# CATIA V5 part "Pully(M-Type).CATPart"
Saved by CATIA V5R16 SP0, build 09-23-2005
Part number: Pully
Bounding box of the stored display mesh (mm): x 0 to 54, y -42.194 to 42.194, z -42.194 to 42.194
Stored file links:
  C:\V5_education\CATIA Data\ASD\Power Transmission Gear Assembly\Assembly Data\Pully(M-Type).CATPart
  C:\V5_education\CATIA Data\ASD\Power Transmission Gear Assembly\Assembly Data\Power Transmission Gear Assembly.CATProduct
  C:\V5_education\CATIA Data\ASD\Power Transmission Gear Assembly\Assembly Data\Power Transmission Gear.CATPart
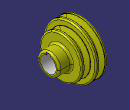
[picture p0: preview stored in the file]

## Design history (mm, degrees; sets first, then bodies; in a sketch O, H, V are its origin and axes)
Set1
  DatumSurface1: linked copy from another document
Set2 "Reference Data"
  Point1 "Center Point": (0, 0, 0)
Body1 (main body)
  Body2
    Sketch1 on zx-plane, origin (0, 0, 0), H (-1, 0, 0), V (0, 0, 1)
      axis line L1 (0, 0) -> (-72.0161, 0)
      line L2 (0, 0) -> (0, 42.2)
      line L3 (0, 42.2) -> (-4.6227, 42.2)
      line L4 (-4.6227, 42.2) -> (-7.547, 33.2)
      line L5 (-7.547, 33.2) -> (-11.453, 33.2)
      line L6 (-11.453, 33.2) -> (-14.3773, 42.2)
      point P6 (-14.3773, 42.2)
      line L7 (-14.3773, 42.2) -> (-19, 42.2)
      line L8 (-19, 42.2) -> (-19, 0)
      point P8 (-19, 0)
      construction line L9 (-19, 39.5) -> (0, 39.5)
      point P9 (-19, 39.5)
      point P10 (0, 39.5)
      construction line L10 (-9.5, 33.2) -> (-9.5, 39.5)
      point P11 (-9.5, 33.2)
      point P12 (-9.5, 39.5)
      point P13 (-13.5, 39.5)
      point P14 (-5.5, 39.5)
      distance L9 H = 39.5
      distance L3 H = 42.2
      distance L10 L2 = 9.5
      distance P13 P14 = 8
      angle L6 L4 = 36
      distance L5 L9 = 6.3
      horizontal: L1 H, L3 H, L5 H, L7 H, L9 H
      vertical: L2 V, L8 V, L10 V
      coincidence: P6 L3, P8 L1, P9 L8, P10 L2, P12 L9, L6 P13, L9 P13, L4 P14, L9 P14
      midpoint: P11 L5
      symmetry: L8 L2 L10, L6 L4 L10
    Shaft1: profile Sketch1, axis Sketch1.L1, angle 360
    Fillet1: radius 2, on edge [face of Shaft1 from Sketch1.L7 | face of Shaft1 from Sketch1.L8]; edge [face of Shaft1 from Sketch1.L2 | face of Shaft1 from Sketch1.L3]
    Fillet2: radius 1, on face of Shaft1 from Sketch1.L5
    Fillet3: radius 0.5, on edge [face of Shaft1 from Sketch1.L6 | face of Shaft1 from Sketch1.L7]; edge [face of Shaft1 from Sketch1.L3 | face of Shaft1 from Sketch1.L4]
  Assemble1: tool Body2
  Body3
    Sketch2 on zx-plane, origin (0, 0, 0), H (-1, 0, 0), V (0, 0, 1)
      axis line L1 (0, 0) -> (-72.0161, 0)
      point P2 (-15, 33.7)
      line L2 (-15, 33.7) -> (-19.6745, 33.7)
      line L3 (-19.6745, 33.7) -> (-22.4261, 24.7)
      line L4 (-22.4261, 24.7) -> (-26.5739, 24.7)
      line L5 (-26.5739, 24.7) -> (-29.3255, 33.7)
      point P6 (-29.3255, 33.7)
      line L6 (-29.3255, 33.7) -> (-34, 33.7)
      point P7 (-34, 33.7)
      line L7 (-34, 33.7) -> (-34, 0)
      point P8 (-34, 0)
      construction line L8 (-34, 31) -> (0.1204, 31)
      point P9 (-34, 31)
      construction line L9 (-24.5, 24.7) -> (-24.5, 31)
      point P11 (-24.5, 24.7)
      point P12 (-24.5, 31)
      point P13 (-28.5, 31)
      point P14 (-20.5, 31)
      line L10 (-15, 33.7) -> (-15, 0)
      point P15 (-15, 0)
      construction line L11 (-9.5, 0) -> (-9.5, 43.4274)
      point P16 (-9.5, 0)
      distance L8 H = 31
      distance L2 H = 33.7
      distance P13 P14 = 8
      angle L5 L3 = 34
      distance L4 L8 = 6.3
      distance L7 V = 34
      distance L11 V = 9.5
      distance L11 L9 = 15
      horizontal: L1 H, L2 H, L4 H, L6 H, L8 H
      coincidence: P6 L2, P8 L1, P9 L7, P12 L8, L5 P13, L8 P13, L3 P14, L8 P14, P15 L1, P16 L1
      vertical: L7 V, L9 V, L10 V, L11 V
      midpoint: P11 L4
      symmetry: L5 L3 L9, P2 P7 L9
    Shaft2: profile Sketch2, axis Sketch2.L1, angle 360
    Fillet4: radius 2, on edge [face of Shaft2 from Sketch2.L6 | face of Shaft2 from Sketch2.L7]; edge [face of Shaft2 from Sketch2.L10 | face of Shaft2 from Sketch2.L2]
    Fillet5: radius 1, on face of Shaft2 from Sketch2.L4
    Fillet6: radius 0.5, on edge [face of Shaft2 from Sketch2.L5 | face of Shaft2 from Sketch2.L6]; edge [face of Shaft2 from Sketch2.L2 | face of Shaft2 from Sketch2.L3]
  Assemble2: tool Body3
  Sketch3 on yz-plane, origin (0, 0, 0), H (0, -1, 0), V (0, 0, 1)
    circle A1 centre (0, 0) radius 17.5
    radius A1 = 17.5
  Pad1: profile Sketch3, direction (1, 0, 0), length 54
  Fillet7: radius 3, on edge [face of Shaft2 from Sketch2.L7 | face of Pad1 from Sketch3.A1]
  Fillet8: radius 3, on end face of Pad1
  Body4
    Sketch4 on yz-plane, origin (0, 0, 0), H (0, -1, 0), V (0, 0, 1)
      circle A1 centre (0, 0) radius 21
      radius A1 = 21
    Pocket1: profile Sketch4, direction (1, 0, 0), length 22
    Fillet9: radius 3, on end face of Pocket1
    Sketch5 on yz-plane, origin (0, 0, 0), H (0, -1, 0), V (0, 0, 1)
      arc A1 centre (0, 0) radius 12.5 from (-3.5, 12) to (3.5, 12) ccw
      line L1 (-3.5, 15.5) -> (3.5, 15.5)
      line L2 (3.5, 15.5) -> (3.5, 12)
      line L3 (-3.5, 12) -> (-3.5, 15.5)
      radius A1 = 12.5
      distance L3 L2 = 7
      distance L1 A1 = 28
      horizontal: L1 H
      vertical: L2 V, L3 V
      symmetry: L3 L2 V
    Pocket2: profile Sketch5, direction (1, 0, 0), length 54
  Assemble3: tool Body4
  AssyPrtSPLIT1: SplitPlane DatumSurface1, _MechModInactiveResultOUT result of AssyPrtSPLIT1, deactivated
